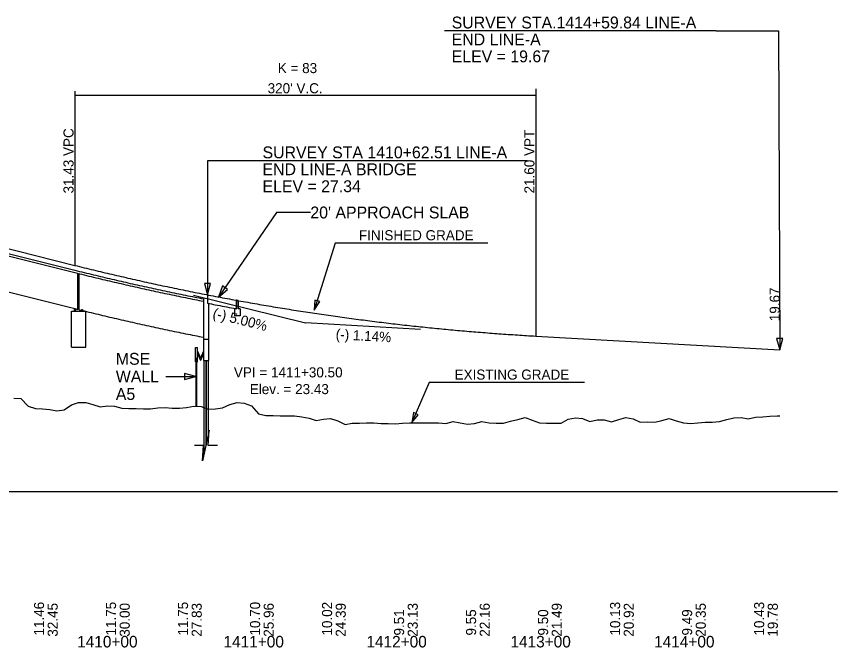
# Model space of a CAD drawing. Extents: x 2360994 to 2383826, y 330623 to 403123.
# Drawn here: x 2373355 to 2373926, y 371764 to 372203 of the extents above; entities that cross this region are included whole.
import ezdxf

# ---------------------------------------------------------------- set-up
doc = ezdxf.new("R2010")
doc.units = 0
for name, color, linetype in [('BR_DETAILS', 7, 'Continuous'), ('BR_STRUCTURAL STEEL', 7, 'Continuous'), ('RD_DDB_GradeTX', 7, 'Continuous'), ('RD_DDB_Profile_EX', 7, 'Continuous'), ('RD_DDB_Profile_Lbl', 7, 'Continuous'), ('RD_DDB_Profile_PR', 7, 'Continuous'), ('RD_DDB_StaTX', 7, 'Continuous'), ('RD_DDB_StripGrade', 7, 'Continuous'), ('RD_DDB_VCLbl', 7, 'Continuous'), ('RD_GPK_Profile_Cell', 7, 'Continuous'), ('RD_PD_MedBWall', 7, 'Continuous'), ('RD_TX_Profile', 7, 'Continuous'), ('RD_XS_Bridge', 7, 'Continuous')]:
    doc.layers.add(name, color=color, linetype=linetype)

msp = doc.modelspace()

# ---------------------------------------------------------------- linework, layer by layer
at = {"layer": 'BR_DETAILS'}
for p, q in [((2373489.29, 371915.58), (2373484.69, 371894.12)), ((2373488.64, 371904.8), (2373489.29, 371915.58)), ((2373485.34, 371904.8), (2373478.99, 371904.8)), ((2373484.69, 371894.12), (2373485.34, 371904.8)), ((2373494.99, 371904.8), (2373488.64, 371904.8))]:
    msp.add_line(p, q, dxfattribs=at)
at = {"layer": 'BR_STRUCTURAL STEEL'}
for p, q in [((2373485.54, 371963.83), (2373485.54, 371898.07)), ((2373486.94, 371963.83), (2373486.94, 371904.61)), ((2373487.04, 371963.83), (2373487.04, 371905.08)), ((2373488.44, 371963.83), (2373488.44, 371911.62))]:
    msp.add_line(p, q, dxfattribs=at)
at = {"layer": 'RD_DDB_GradeTX'}
for p in [(2373478.45, 372009.41), (2373635.94, 371985.45)]:
    msp.add_line(p, (2373556.07, 371990.01), dxfattribs=at)
at = {"layer": 'RD_DDB_Profile_EX'}
for points in [[(2373353.57, 371937.64), (2373358.57, 371937.56), (2373363.57, 371932.19), (2373368.57, 371930.48), (2373373.57, 371930.4)], [(2373373.57, 371930.4), (2373378.57, 371929.88), (2373383.57, 371929.01), (2373388.57, 371929.54), (2373393.57, 371933.12), (2373398.57, 371934.67), (2373403.57, 371934.64), (2373408.57, 371933.27), (2373413.57, 371931.76), (2373418.57, 371932.39), (2373423.57, 371932.22), (2373428.57, 371930.7), (2373433.57, 371930.68), (2373438.57, 371930.68), (2373443.57, 371930.35), (2373448.57, 371930.33), (2373453.57, 371931.13), (2373458.57, 371931.31), (2373463.57, 371930.88), (2373468.57, 371930.75), (2373473.57, 371931.26), (2373478.57, 371932.21), (2373483.57, 371931.96), (2373488.57, 371930.19), (2373493.57, 371930.41), (2373498.57, 371931), (2373503.57, 371933.32), (2373508.57, 371934.82), (2373513.57, 371934.32), (2373518.57, 371932.38), (2373523.57, 371926.78), (2373528.57, 371925.79), (2373533.57, 371925.65), (2373538.57, 371925.49), (2373543.57, 371925.39), (2373548.57, 371925.38), (2373553.57, 371924.85), (2373558.57, 371923.9), (2373563.57, 371922.22), (2373568.57, 371923.23), (2373573.57, 371923.66), (2373578.57, 371922.03), (2373583.57, 371919.56), (2373588.57, 371920.4), (2373593.57, 371920.39), (2373598.57, 371920.59), (2373603.57, 371920.68), (2373608.57, 371920.19), (2373613.57, 371920.09), (2373618.57, 371919.97), (2373623.57, 371920.33), (2373628.57, 371920.56), (2373633.57, 371920.59), (2373638.57, 371920.5), (2373643.57, 371920.6), (2373648.57, 371920.6), (2373653.57, 371920.16), (2373658.57, 371921.62), (2373663.57, 371920.72), (2373668.57, 371919.68), (2373673.57, 371920.07), (2373678.57, 371921.5), (2373683.57, 371920.6), (2373688.57, 371920.31), (2373693.57, 371920.34), (2373698.57, 371921.8), (2373703.57, 371922.98), (2373708.57, 371924.26), (2373713.57, 371922.53), (2373718.57, 371920.73), (2373723.57, 371920.44), (2373728.57, 371920.31), (2373733.57, 371920.39), (2373738.57, 371923.27), (2373743.57, 371924.01), (2373748.57, 371923.7), (2373753.57, 371921.45), (2373758.57, 371922.62), (2373763.57, 371922.81), (2373768.57, 371921.2), (2373773.57, 371922.97), (2373778.57, 371924.38), (2373783.57, 371923.43), (2373788.57, 371921.04), (2373793.57, 371921.4), (2373798.57, 371921.04), (2373803.57, 371922.15), (2373808.57, 371923.66), (2373813.57, 371921.99), (2373818.57, 371920.7), (2373823.57, 371920.25), (2373828.57, 371920.5), (2373833.57, 371921.15), (2373838.57, 371921.15), (2373843.57, 371921.57), (2373848.57, 371922.87), (2373853.57, 371923.98), (2373858.57, 371924.22), (2373863.57, 371923.38), (2373868.57, 371924.55), (2373873.57, 371924.88)], [(2373873.57, 371924.88), (2373878.57, 371925.21), (2373883.57, 371925.46), (2373885.41, 371925.47)]]:
    msp.add_lwpolyline(points, dxfattribs=at)
at = {"layer": 'RD_DDB_Profile_PR'}
for p, q in [((2373185.57, 372082.63), (2373396.07, 372030.01)), ((2373716.07, 371980.89), (2373885.41, 371971.23))]:
    msp.add_line(p, q, dxfattribs=at)
msp.add_spline([(2373396.07, 372030.01), (2373402.47, 372028.42), (2373408.87, 372026.86), (2373415.27, 372025.32), (2373421.67, 372023.8), (2373428.07, 372022.32), (2373434.47, 372020.85), (2373440.87, 372019.41), (2373447.27, 372018), (2373453.67, 372016.61), (2373460.07, 372015.24), (2373466.47, 372013.9), (2373472.87, 372012.59), (2373479.27, 372011.29), (2373485.67, 372010.03), (2373492.07, 372008.79), (2373498.47, 372007.57), (2373504.87, 372006.38), (2373511.27, 372005.21), (2373517.67, 372004.07), (2373524.07, 372002.95), (2373530.47, 372001.85), (2373536.87, 372000.78), (2373543.27, 371999.74), (2373549.67, 371998.72), (2373556.07, 371997.73), (2373562.47, 371996.76), (2373568.87, 371995.81), (2373575.27, 371994.89), (2373581.67, 371993.99), (2373588.07, 371993.12), (2373594.47, 371992.28), (2373600.87, 371991.45), (2373607.27, 371990.66), (2373613.67, 371989.89), (2373620.07, 371989.14), (2373626.47, 371988.41), (2373632.87, 371987.72), (2373639.27, 371987.04), (2373645.67, 371986.39), (2373652.07, 371985.77), (2373658.47, 371985.17), (2373664.87, 371984.6), (2373671.27, 371984.05), (2373677.67, 371983.52), (2373684.07, 371983.02), (2373690.47, 371982.54), (2373696.87, 371982.09), (2373703.27, 371981.67), (2373709.67, 371981.26), (2373716.07, 371980.89)], degree=3, dxfattribs=at)
at = {"layer": 'RD_DDB_VCLbl'}
for p, q in [((2373716.07, 372152.65), (2373716.07, 371980.89)), ((2373396.07, 372151.1), (2373396.07, 372030.01)), ((2373396.07, 372148.36), (2373716.07, 372148.36))]:
    msp.add_line(p, q, dxfattribs=at)
at = {"layer": 'RD_GPK_Profile_Cell'}
msp.add_line((2368825.57, 371872.88), (2373925.57, 371872.88), dxfattribs=at)
at = {"layer": 'RD_PD_MedBWall'}
for p, q in [((2373479.63, 371962.99), (2373479.63, 371972.99)), ((2373479.63, 371972.99), (2373481.13, 371972.99)), ((2373481.13, 371962.99), (2373481.13, 371972.99)), ((2373481.13, 371970.49), (2373483.13, 371965.49)), ((2373481.13, 371968.83), (2373483.13, 371963.83)), ((2373485.24, 371970.49), (2373483.24, 371965.49)), ((2373485.24, 371968.83), (2373483.24, 371963.83)), ((2373480.13, 371932.13), (2373480.13, 371965.49)), ((2373480.13, 371965.49), (2373480.63, 371965.49)), ((2373480.63, 371932.1), (2373480.63, 371965.49)), ((2373479.63, 371962.99), (2373480.13, 371962.99)), ((2373480.63, 371962.99), (2373481.13, 371962.99))]:
    msp.add_line(p, q, dxfattribs=at)
at = {"layer": 'RD_TX_Profile'}
for p, q in [((2373841.38, 372192.89), (2373652.62, 372192.89)), ((2373710.05, 372102.66), (2373521.28, 372102.66)), ((2373682.79, 372045.48), (2373588.23, 372045.48)), ((2373749.79, 371948.65), (2373654.66, 371948.65))]:
    msp.add_line(p, q, dxfattribs=at)
for points in [[(2373841.38, 372192.89), (2373884.56, 372192.89), (2373885.41, 371971.23)], [(2373521.28, 372102.66), (2373488.07, 372102.66), (2373488.07, 372009.56)], [(2373559.49, 372066.77), (2373536.03, 372066.77), (2373495.8, 372008.02)], [(2373588.23, 372045.48), (2373576.62, 372045.48), (2373562.25, 371998.89)], [(2373459.03, 371952.86), (2373465.21, 371952.86), (2373480.04, 371952.86)], [(2373654.66, 371948.65), (2373641.97, 371948.65), (2373630.03, 371920.78)]]:
    msp.add_lwpolyline(points, dxfattribs=at)
for points in [[(2373485.94, 372017.51), (2373488.07, 372009.56), (2373490.21, 372017.51)], [(2373498.54, 372015.78), (2373495.8, 372008.02), (2373502.05, 372013.37)], [(2373562.51, 372005.89), (2373562.25, 371998.89), (2373565.97, 372004.82)], [(2373883.24, 371979.18), (2373885.41, 371971.23), (2373887.51, 371979.2)], [(2373472.09, 371950.73), (2373480.04, 371952.86), (2373472.09, 371954.99)], [(2373631.03, 371927.71), (2373630.03, 371920.78), (2373634.36, 371926.28)]]:
    msp.add_lwpolyline(points, close=True, dxfattribs=at)
at = {"layer": 'RD_XS_Bridge'}
for p, q in [((2373190.57, 372078.05), (2373396.07, 372026.67)), ((2373190.57, 372076.38), (2373396.07, 372025.01)), ((2373281.49, 372028.61), (2373396.07, 371999.97)), ((2373398.07, 371999.47), (2373398.07, 372024.51)), ((2373399.07, 371999.22), (2373399.07, 372024.26)), ((2373488.07, 372009.56), (2373488.07, 372003.72)), ((2373485.24, 372006.78), (2373485.24, 371963.83)), ((2373488.74, 372003.59), (2373488.74, 371963.83)), ((2373509.41, 372005.55), (2373508.07, 372005.79)), ((2373508.07, 372005.77), (2373508.07, 371999.94)), ((2373508.07, 372005.77), (2373508.07, 371999.94)), ((2373508.16, 372005.75), (2373508.07, 372005.77)), ((2373508.16, 372005.75), (2373508.16, 371999.94)), ((2373508.16, 371999.94), (2373508.16, 372005.75)), ((2373509.41, 372005.53), (2373509.41, 371999.94)), ((2373393.57, 371973.1), (2373393.57, 371998.1)), ((2373393.57, 371998.1), (2373398.57, 371998.1)), ((2373396.07, 371999.97), (2373398.07, 371999.47)), ((2373398.57, 371998.1), (2373403.57, 371998.1)), ((2373403.57, 371973.1), (2373403.57, 371998.1)), ((2373506.91, 372000.15), (2373506.91, 371994.94)), ((2373508.16, 371999.94), (2373508.07, 371999.94)), ((2373508.07, 371999.94), (2373508.16, 371999.94)), ((2373510.66, 371999.94), (2373509.41, 371999.94)), ((2373510.66, 371999.94), (2373510.66, 371994.94)), ((2373510.66, 371994.94), (2373506.91, 371994.94)), ((2373485.24, 371978.83), (2373488.74, 371978.83)), ((2373393.57, 371973.1), (2373403.57, 371973.1)), ((2373485.24, 371963.83), (2373488.74, 371963.83))]:
    msp.add_line(p, q, dxfattribs=at)
for points in [[(2373395.82, 371998.1), (2373395.82, 371999.35), (2373396.32, 371999.35), (2373396.32, 371998.1)], [(2373400.82, 371998.1), (2373400.82, 371999.35), (2373401.32, 371999.35), (2373401.32, 371998.1)]]:
    msp.add_lwpolyline(points, close=True, dxfattribs=at)
for points in [[(2373396.07, 372026.67), (2373402.47, 372025.09), (2373408.87, 372023.52), (2373415.27, 372021.98), (2373421.67, 372020.47), (2373428.07, 372018.98), (2373434.47, 372017.52), (2373440.87, 372016.08), (2373447.27, 372014.66), (2373453.67, 372013.27), (2373460.07, 372011.91), (2373466.47, 372010.57), (2373472.87, 372009.25), (2373479.27, 372007.96), (2373485.24, 372006.77)], [(2373396.07, 372025.01), (2373402.47, 372023.42), (2373408.87, 372021.86), (2373415.27, 372020.32), (2373421.67, 372018.8), (2373428.07, 372017.32), (2373434.47, 372015.85), (2373440.87, 372014.41), (2373447.27, 372013), (2373453.67, 372011.61), (2373460.07, 372010.24), (2373466.47, 372008.9), (2373472.87, 372007.59), (2373479.27, 372006.29), (2373485.24, 372005.11)], [(2373488.07, 372003.72), (2373493.51, 372002.67), (2373499.91, 372001.45), (2373506.31, 372000.26), (2373508.07, 371999.94)], [(2373399.07, 371999.22), (2373402.47, 371998.38), (2373408.87, 371996.82), (2373415.27, 371995.28), (2373421.67, 371993.77), (2373428.07, 371992.28), (2373434.47, 371990.81), (2373440.87, 371989.37), (2373447.27, 371987.96), (2373453.67, 371986.57), (2373460.07, 371985.2), (2373466.47, 371983.86), (2373472.87, 371982.55), (2373479.27, 371981.26), (2373485.24, 371980.07)]]:
    msp.add_spline(points, degree=3, dxfattribs=at)

# ---------------------------------------------------------------- texts
at = {"layer": 'RD_DDB_GradeTX'}
for s, rotation, p in [('(-) 5.00%', 345.9638, (2373491.2, 371993.65)), ('(-) 1.14%', 356.7377, (2373576.97, 371978.76))]:
    msp.add_text(s, height=7, rotation=rotation, dxfattribs=at).set_placement(p)
at = {"layer": 'RD_DDB_Profile_Lbl'}
msp.add_text('19.67', height=7, rotation=90, dxfattribs=at).set_placement((2373885.41, 371991.23))
for s, p in [('VPI = 1411+30.50', (2373506.41, 371952.19)), ('Elev. = 23.43', (2373517.44, 371940.55))]:
    msp.add_text(s, height=7, dxfattribs=at).set_placement(p)
at = {"layer": 'RD_DDB_StaTX'}
for s, p in [('1410+00', (2373397.57, 371764.56)), ('1411+00', (2373499.18, 371764.56)), ('1412+00', (2373598.38, 371764.56)), ('1413+00', (2373698.41, 371764.56)), ('1414+00', (2373798.17, 371764.56))]:
    msp.add_text(s, height=8, dxfattribs=at).set_placement(p)
at = {"layer": 'RD_DDB_StripGrade'}
for s, p in [('31.43 VPC', (2373395.07, 372080.01)), ('21.60 VPT', (2373715.07, 372080.01)), ('11.46', (2373374.59, 371772.81)), ('32.45', (2373384.08, 371772.02)), ('11.75', (2373424.59, 371772.81)), ('30.00', (2373434.08, 371772.02)), ('11.75', (2373474.59, 371772.81)), ('27.83', (2373484.08, 371772.02)), ('10.70', (2373524.59, 371772.81)), ('25.96', (2373534.08, 371772.02)), ('10.02', (2373574.59, 371772.81)), ('24.39', (2373584.08, 371772.02)), ('23.13', (2373634.08, 371772.02)), ('22.16', (2373684.08, 371772.02)), ('21.49', (2373734.08, 371772.02)), ('10.13', (2373774.59, 371772.81)), ('20.92', (2373784.08, 371772.02)), ('20.35', (2373834.08, 371772.02)), ('10.43', (2373874.59, 371772.81)), ('19.78', (2373884.08, 371772.02)), ('9.51', (2373624.59, 371772.81)), ('9.55', (2373674.59, 371772.81)), ('9.50', (2373724.59, 371772.81)), ('9.49', (2373824.59, 371772.81))]:
    msp.add_text(s, height=7, rotation=90, dxfattribs=at).set_placement(p)
at = {"layer": 'RD_DDB_VCLbl'}
for s, p in [('K = 83', (2373536.88, 372163.61)), ("320' V.C.", (2373529.83, 372149.61))]:
    msp.add_text(s, height=7, dxfattribs=at).set_placement(p)
at = {"layer": 'RD_TX_Profile'}
for s, height, p in [('SURVEY STA.1414+59.84 LINE-A', 8.2353, (2373657.62, 372194.65)), ('END LINE-A', 8.235, (2373657.62, 372182.89)), ('ELEV = 19.67', 8.2353, (2373657.62, 372171.13)), ('SURVEY STA 1410+62.51 LINE-A', 8.2353, (2373526.28, 372104.42)), ('END LINE-A BRIDGE', 8.2353, (2373526.28, 372092.66)), ('ELEV = 27.34', 8.2353, (2373526.28, 372080.89)), ("20' APPROACH SLAB", 8.2353, (2373559.49, 372062.65)), ('FINISHED GRADE', 7, (2373593.23, 372047.48)), ('MSE', 8.235, (2373424.42, 371960.98)), ('EXISTING GRADE', 7, (2373659.66, 371950.65)), ('WALL', 8.235, (2373424.42, 371948.74)), ('A5', 8.235, (2373424.42, 371936.5))]:
    msp.add_text(s, height=height, dxfattribs=at).set_placement(p)

doc.saveas('drawing.dxf')
